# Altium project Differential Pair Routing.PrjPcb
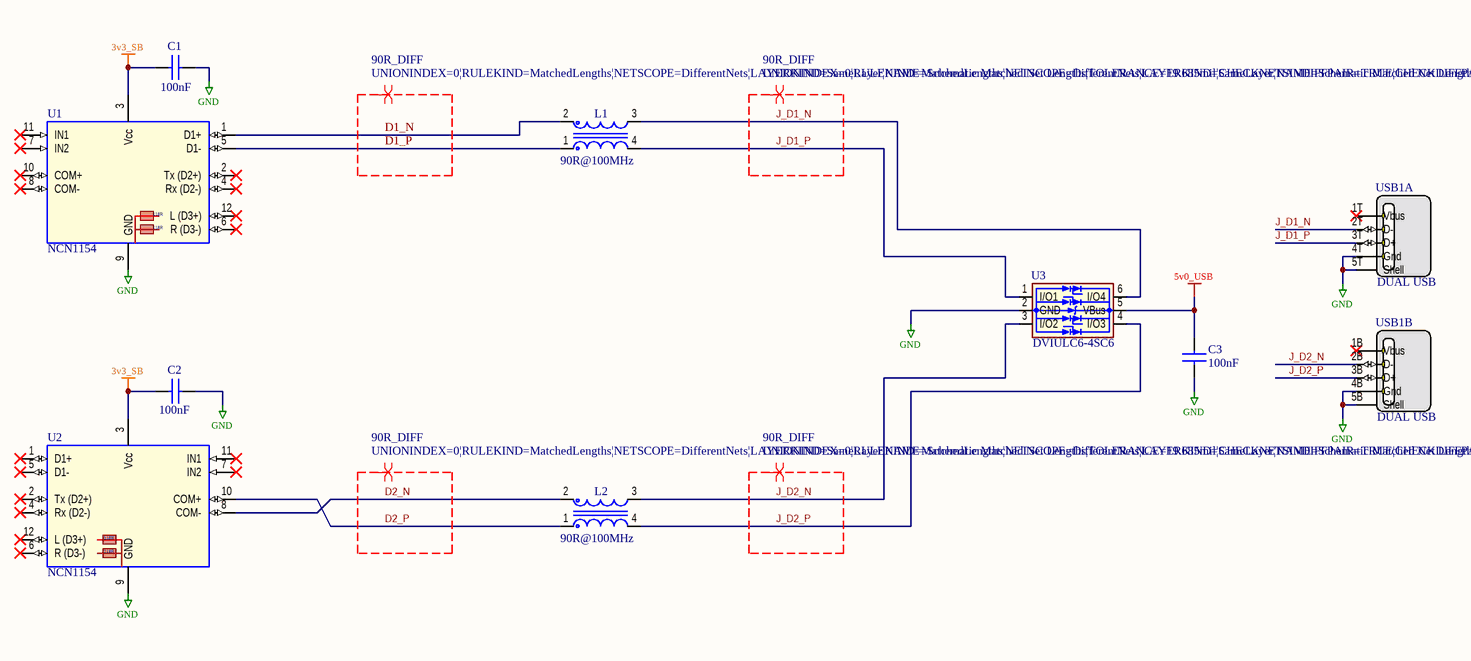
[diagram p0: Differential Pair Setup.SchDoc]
1 sheet, 9 parts. Net scope: global (net labels, ports and power ports of the same name join across sheets).
Board file: Diff Pair Routing.PcbDoc

## Sheet Differential Pair Setup.SchDoc
size 431 x 279 mm; Organization: ORGANIZATION; Address1: ADDRESS 1; Address2: ADDRESS 2; Address3: ADDRESS 3; Address4: ADDRESS 4; Revision: -; SheetNumber: 1; SheetTotal: 1; ENG_APP_DATE: --/--/--; DSN_APP_DATE: --/--/--; CHK_APP_DATE: --/--/--

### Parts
C1  100nF  [CC0402]
C2  100nF  [CC0402]
C3  100nF  [CC0402]
L1  90R@100MHz  [ACM2012]
L2  90R@100MHz  [ACM2012]
U1  NCN1154  [UQFN12]
U2  NCN1154  [UQFN12]
U3  DVIULC6-4SC6  [SOT23-6L]
USB1  DUAL USB  [USB-A_RA_DUAL]  (parts A,B of 2)

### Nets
3v3_SB: C1.2 C2.2 U1.3(Vcc) U2.3(Vcc)
5v0_USB: C3.1 U3.5(VBus)
GND: C1.1 C2.1 C3.2 U1.9(GND) U2.9(GND) U3.2(GND) USB1.4B(Gnd) USB1.4T(Gnd) USB1.5B(Shell) USB1.5T(Shell)
D1_N: L1.2 U1.1(D1+)
D1_P: L1.1 U1.5(D1-)
D2_N: L2.2 U2.8(COM-)
D2_P: L2.1 U2.10(COM+)
J_D1_N: L1.3 U3.6(I/O4) USB1.2T(D-)
J_D1_P: L1.4 U3.1(I/O1) USB1.3T(D+)
J_D2_N: L2.3 U3.3(I/O2) USB1.2B(D-)
J_D2_P: L2.4 U3.4(I/O3) USB1.3B(D+)

Not connected (* = marked no-connect by the designer): U1 2(Tx_(D2+))* 4(Rx_(D2-))* 6(R_(D3-))* 7(IN2)* 8(COM-)* 10(COM+)* 11(IN1)* 12(L_(D3+))*; U2 1(D1+)* 2(Tx_(D2+))* 4(Rx_(D2-))* 5(D1-)* 6(R_(D3-))* 7(IN2)* 11(IN1)* 12(L_(D3+))*; USB1 1B(Vbus)* 1T(Vbus)*

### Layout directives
differential pair; rule Matched Net Lengths [Tolerance = 0.5mm]; differential pair class 90R_DIFF: D1_N, D1_P, D2_N, D2_P, J_D1_N, J_D1_P, J_D2_N, J_D2_P

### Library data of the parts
C1-C3 = CAP_100nF: Cap, 100nF, X7R, 16V, ±10%, CC0402
L1 L2 = FILTER: CMNCK, 90R@100MHz, 50V, 400mA, ACM2012
U1 U2 = USB_UART: 3:1 High-Speed USB /UART/Auido Mux
U3 = ESD_Protector: 4-chl Ultra-Low Capacitance ESD protector with TVS diode
USB1 = USB: RoHS compliant or Toby - KUSB-AS2N-WHT or Toby - KUSB-AS2N-BLK or 2EUK - UBAR-08S or 2EUK (Oupiin) - 8968-A08CRW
